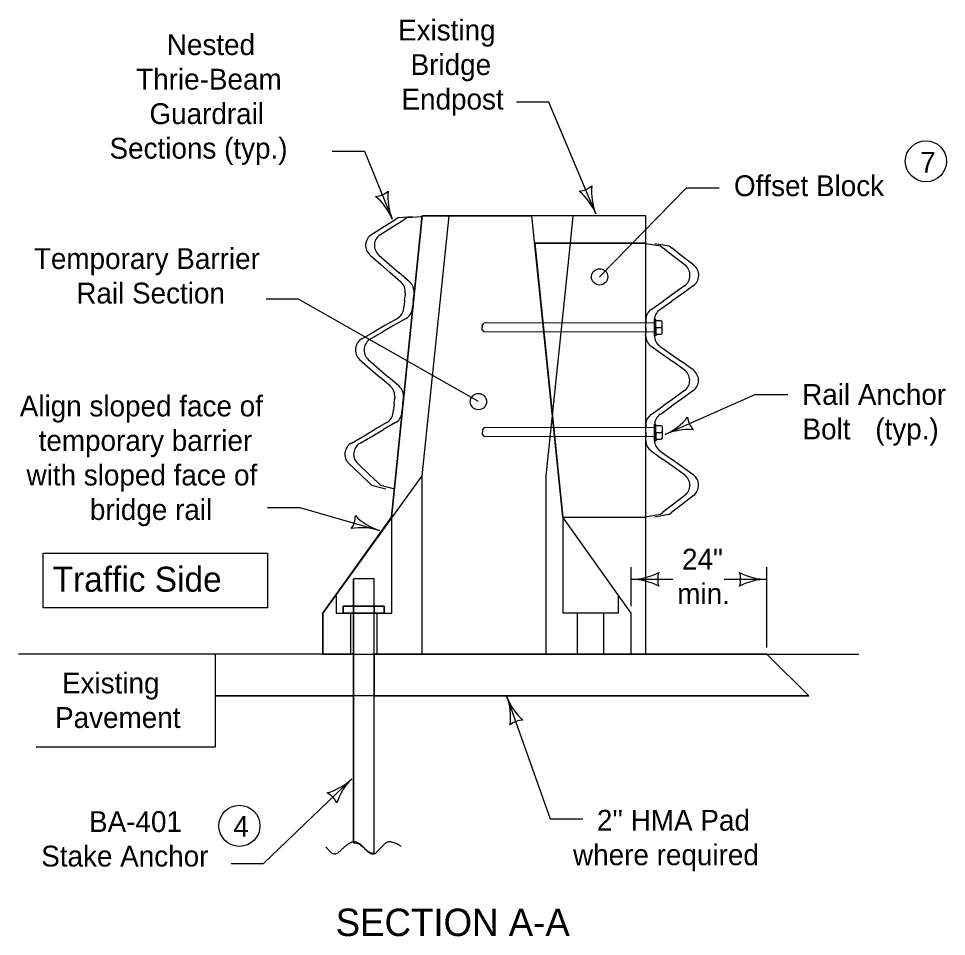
# Model space of a CAD drawing. Extents: x -2137026 to -2131464, y -2138478 to -2136524.
# Drawn here: x -2136990 to -2136313, y -2137286 to -2136616 of the extents above; entities that cross this region are included whole.
import ezdxf

# ---------------------------------------------------------------- set-up
doc = ezdxf.new("R2010")
doc.units = 0
for name, color, linetype in [('conPaving', 7, 'Continuous'), ('Level 2', 7, 'Continuous'), ('Level 3', 7, 'Continuous'), ('Level 41', 7, 'Continuous'), ('Level 9', 7, 'Continuous')]:
    doc.layers.add(name, color=color, linetype=linetype)

msp = doc.modelspace()

# ---------------------------------------------------------------- linework, layer by layer
at = {"layer": 'conPaving'}
for p, q in [((-2136695.79, -2136949.91), (-2136695.79, -2137079.91)), ((-2136605.35, -2136949.91), (-2136605.35, -2137079.91))]:
    msp.add_line(p, q, dxfattribs=at)
at = {"layer": 'Level 2'}
for p, q in [((-2136603.25, -2136676.99), (-2136626.86, -2136676.99)), ((-2136568.93, -2136758.59), (-2136603.25, -2136676.99)), ((-2136761.29, -2136712.88), (-2136737.68, -2136712.88)), ((-2136737.68, -2136712.88), (-2136717.45, -2136762.45)), ((-2136566.1, -2136804.59), (-2136502.64, -2136739.51)), ((-2136502.64, -2136739.51), (-2136479, -2136739.51)), ((-2136718.04, -2136979.91), (-2136695.54, -2136759.91)), ((-2136695.54, -2136759.91), (-2136615.54, -2136759.91)), ((-2136593.04, -2136979.91), (-2136615.54, -2136759.91)), ((-2136723.01, -2136767.65), (-2136715.47, -2136762.89)), ((-2136716.61, -2136767.65), (-2136709.07, -2136762.89)), ((-2136713.24, -2136761.48), (-2136715.47, -2136762.89)), ((-2136702.53, -2136760.66), (-2136713.24, -2136761.48)), ((-2136706.84, -2136761.48), (-2136709.07, -2136762.89)), ((-2136696.13, -2136760.66), (-2136706.84, -2136761.48)), ((-2136732.5, -2136773.64), (-2136723.01, -2136767.65)), ((-2136726.11, -2136773.64), (-2136716.61, -2136767.65)), ((-2136532.36, -2136780.13), (-2136521.78, -2136782.01)), ((-2136525.96, -2136780.13), (-2136515.39, -2136782.01)), ((-2136521.78, -2136782.01), (-2136519.7, -2136783.63)), ((-2136512.67, -2136789.12), (-2136519.7, -2136783.63)), ((-2136515.39, -2136782.01), (-2136513.31, -2136783.63)), ((-2136506.27, -2136789.12), (-2136513.31, -2136783.63)), ((-2136733.67, -2136788.69), (-2136725.87, -2136795.49)), ((-2136727.27, -2136788.69), (-2136719.47, -2136795.49)), ((-2136503.82, -2136796.02), (-2136512.67, -2136789.12)), ((-2136497.42, -2136796.02), (-2136506.27, -2136789.12)), ((-2136725.87, -2136795.49), (-2136719.15, -2136801.35)), ((-2136719.47, -2136795.49), (-2136712.76, -2136801.35)), ((-2136711.14, -2136808.34), (-2136719.15, -2136801.35)), ((-2136704.75, -2136808.34), (-2136712.76, -2136801.35)), ((-2136504.16, -2136811.12), (-2136512.6, -2136817.11)), ((-2136497.77, -2136811.12), (-2136506.2, -2136817.11)), ((-2136785.87, -2136820.95), (-2136809.47, -2136820.95)), ((-2136654.56, -2136895.65), (-2136785.87, -2136820.95)), ((-2136708.5, -2136821.98), (-2136708.13, -2136818.1)), ((-2136707.96, -2136816.35), (-2136708.13, -2136818.1)), ((-2136702.11, -2136821.98), (-2136701.73, -2136818.1)), ((-2136701.56, -2136816.35), (-2136701.73, -2136818.1)), ((-2136512.6, -2136817.11), (-2136519.86, -2136822.27)), ((-2136506.2, -2136817.11), (-2136513.47, -2136822.27)), ((-2136709.05, -2136827.61), (-2136708.85, -2136825.57)), ((-2136708.49, -2136821.84), (-2136708.85, -2136825.57)), ((-2136702.66, -2136827.61), (-2136702.46, -2136825.57)), ((-2136702.09, -2136821.84), (-2136702.46, -2136825.57)), ((-2136528.53, -2136828.43), (-2136519.86, -2136822.27)), ((-2136522.13, -2136828.43), (-2136513.47, -2136822.27)), ((-2136713.73, -2136834.85), (-2136722.92, -2136840.15)), ((-2136707.33, -2136834.85), (-2136716.52, -2136840.15)), ((-2136722.92, -2136840.15), (-2136730.63, -2136844.6)), ((-2136716.52, -2136840.15), (-2136724.24, -2136844.6)), ((-2136532.51, -2136841.59), (-2136532.52, -2136845.35)), ((-2136532.51, -2136841.74), (-2136532.5, -2136837.84)), ((-2136532.5, -2136836.08), (-2136532.5, -2136837.84)), ((-2136526.12, -2136841.59), (-2136526.13, -2136845.35)), ((-2136526.12, -2136841.74), (-2136526.11, -2136837.84)), ((-2136526.1, -2136836.08), (-2136526.11, -2136837.84)), ((-2136739.62, -2136849.78), (-2136730.63, -2136844.6)), ((-2136733.23, -2136849.78), (-2136724.24, -2136844.6)), ((-2136532.53, -2136847.39), (-2136532.52, -2136845.35)), ((-2136526.13, -2136847.39), (-2136526.13, -2136845.35)), ((-2136528.6, -2136855.06), (-2136519.98, -2136861.25)), ((-2136522.2, -2136855.06), (-2136513.59, -2136861.25)), ((-2136519.98, -2136861.25), (-2136512.75, -2136866.45)), ((-2136513.59, -2136861.25), (-2136506.35, -2136866.45)), ((-2136741.36, -2136864.8), (-2136733.29, -2136871.84)), ((-2136734.97, -2136864.8), (-2136726.89, -2136871.84)), ((-2136504.32, -2136872.5), (-2136512.75, -2136866.45)), ((-2136497.92, -2136872.5), (-2136506.35, -2136866.45)), ((-2136733.29, -2136871.84), (-2136726.57, -2136877.7)), ((-2136726.89, -2136871.84), (-2136720.18, -2136877.7)), ((-2136718.84, -2136884.44), (-2136726.57, -2136877.7)), ((-2136712.44, -2136884.44), (-2136720.18, -2136877.7)), ((-2136504.08, -2136887.61), (-2136512.82, -2136893.82)), ((-2136497.68, -2136887.61), (-2136506.42, -2136893.82)), ((-2136716.17, -2136897.77), (-2136715.8, -2136894.03)), ((-2136715.65, -2136892.45), (-2136715.8, -2136894.03)), ((-2136709.77, -2136897.77), (-2136709.41, -2136894.03)), ((-2136709.25, -2136892.45), (-2136709.41, -2136894.03)), ((-2136512.82, -2136893.82), (-2136520.08, -2136898.98)), ((-2136452.33, -2136890.49), (-2136518.23, -2136919.57)), ((-2136506.42, -2136893.82), (-2136513.69, -2136898.98)), ((-2136452.33, -2136890.49), (-2136428.72, -2136890.49)), ((-2136716.75, -2136903.71), (-2136716.53, -2136901.5)), ((-2136716.17, -2136897.77), (-2136716.53, -2136901.5)), ((-2136710.35, -2136903.71), (-2136710.14, -2136901.5)), ((-2136709.77, -2136897.77), (-2136710.14, -2136901.5)), ((-2136528.45, -2136904.92), (-2136520.08, -2136898.98)), ((-2136522.05, -2136904.92), (-2136513.69, -2136898.98)), ((-2136738.04, -2136920.53), (-2136730.32, -2136916.08)), ((-2136731.64, -2136920.53), (-2136723.92, -2136916.08)), ((-2136721.42, -2136910.96), (-2136730.32, -2136916.08)), ((-2136715.03, -2136910.96), (-2136723.92, -2136916.08)), ((-2136532.43, -2136917.91), (-2136532.42, -2136914.16)), ((-2136532.42, -2136912.57), (-2136532.42, -2136914.16)), ((-2136526.04, -2136917.91), (-2136526.03, -2136914.16)), ((-2136526.02, -2136912.57), (-2136526.03, -2136914.16)), ((-2136747.32, -2136925.88), (-2136738.04, -2136920.53)), ((-2136740.92, -2136925.88), (-2136731.64, -2136920.53)), ((-2136532.45, -2136923.89), (-2136532.44, -2136921.66)), ((-2136532.43, -2136917.91), (-2136532.44, -2136921.66)), ((-2136526.04, -2136917.91), (-2136526.05, -2136921.66)), ((-2136526.05, -2136923.89), (-2136526.05, -2136921.66)), ((-2136528.52, -2136931.56), (-2136520.18, -2136937.54)), ((-2136522.12, -2136931.56), (-2136513.78, -2136937.54)), ((-2136749.09, -2136940.88), (-2136740.68, -2136948.82)), ((-2136742.69, -2136940.88), (-2136734.28, -2136948.82)), ((-2136512.94, -2136942.74), (-2136520.18, -2136937.54)), ((-2136506.54, -2136942.74), (-2136513.78, -2136937.54)), ((-2136504.24, -2136948.99), (-2136512.94, -2136942.74)), ((-2136497.84, -2136948.99), (-2136506.54, -2136942.74)), ((-2136740.68, -2136948.82), (-2136734.2, -2136954.95)), ((-2136734.28, -2136948.82), (-2136727.8, -2136954.95)), ((-2136732.53, -2136956.53), (-2136734.2, -2136954.95)), ((-2136732.53, -2136956.53), (-2136722.18, -2136959.4)), ((-2136726.13, -2136956.53), (-2136727.8, -2136954.95)), ((-2136726.13, -2136956.53), (-2136715.78, -2136959.4)), ((-2136503.97, -2136964.09), (-2136513.13, -2136971.15)), ((-2136497.58, -2136964.09), (-2136506.73, -2136971.15)), ((-2136808.55, -2136972.85), (-2136784.95, -2136972.85)), ((-2136784.95, -2136972.85), (-2136726.85, -2136989.7)), ((-2136522.01, -2136978.01), (-2136520.19, -2136976.6)), ((-2136513.13, -2136971.15), (-2136520.19, -2136976.6)), ((-2136515.61, -2136978.01), (-2136513.79, -2136976.6)), ((-2136506.73, -2136971.15), (-2136513.79, -2136976.6)), ((-2136768.04, -2137049.91), (-2136718.04, -2136979.91)), ((-2136543.04, -2137049.91), (-2136593.04, -2136979.91)), ((-2136522.01, -2136978.01), (-2136532.59, -2136979.84)), ((-2136515.61, -2136978.01), (-2136526.2, -2136979.84)), ((-2136543.04, -2137044.92), (-2136543.04, -2137016.56)), ((-2136444, -2137075.15), (-2136444, -2137016.56)), ((-2136543.04, -2137025.32), (-2136512.63, -2137025.32)), ((-2136475.31, -2137025.32), (-2136444, -2137025.32)), ((-2136768.04, -2137079.91), (-2136768.04, -2137049.91)), ((-2136543.04, -2137079.91), (-2136543.04, -2137049.91)), ((-2136768.04, -2137079.91), (-2136543.04, -2137079.91)), ((-2136633.74, -2137111.03), (-2136602.11, -2137200.07)), ((-2136811.38, -2137232.71), (-2136746.96, -2137170.91)), ((-2136602.11, -2137200.07), (-2136578.5, -2137200.07)), ((-2136834.98, -2137232.71), (-2136811.38, -2137232.71))]:
    msp.add_line(p, q, dxfattribs=at)
for centre in [(-2136328.04, -2136720.21), (-2136828.99, -2137205.23)]:
    msp.add_circle(centre, 15, dxfattribs=at)
for centre, radius, start, end in [((-2136582.37, -2136725.59), 16.42, 274.42912, 309.89582), ((-2136529.57, -2136742.56), 42.5, 174.08998, 202.16247), ((-2136730.92, -2136729.46), 16.42, 274.46679, 309.93349), ((-2136756.8, -2136778.51), 42.5, 22.20014, 50.27263), ((-2136678.11, -2136746.4), 42.5, 174.12765, 202.20014), ((-2136608.29, -2136774.63), 42.5, 22.16247, 50.23496), ((-2136535.24, -2136880.63), 42.5, 293.59825, 321.67074), ((-2136485.57, -2136905.31), 16.42, 185.8649, 221.3316), ((-2136501.21, -2136958.52), 42.5, 85.52576, 113.59825), ((-2136760.78, -2136978.8), 16.42, 324.45544, 359.92214), ((-2136713.85, -2136949.23), 42.5, 224.1163, 252.18879), ((-2136739.85, -2137030.16), 42.5, 72.18879, 100.26128), ((-2136543.04, -2136982.82), 42.5, 270, 298.07249), ((-2136507.4, -2137025.32), 16.42, 162.26665, 197.73335), ((-2136479.64, -2137025.32), 16.42, 342.26665, 17.73335), ((-2136444, -2136982.82), 42.5, 241.92751, 270), ((-2136543.04, -2137067.82), 42.5, 61.92751, 90), ((-2136444, -2137067.82), 42.5, 90, 118.07249), ((-2136593.86, -2137096.35), 42.5, 200.20763, 228.28012), ((-2136673.63, -2137125.71), 42.5, 352.13514, 20.20763), ((-2136621.43, -2137144.47), 16.42, 92.47427, 127.94098), ((-2136776.38, -2137140.24), 42.5, 285.73709, 313.80957), ((-2136717.54, -2137201.58), 42.5, 133.80957, 161.88206), ((-2136772.68, -2137195.58), 16.42, 26.07622, 61.54292)]:
    msp.add_arc(centre, radius, start, end, dxfattribs=at)
for centre, major_axis, start_param, end_param in [((-2136727.42, -2136781.6), (9.43, -0.92), 2.229659, 4.096128), ((-2136721.03, -2136781.6), (9.43, -0.92), 2.229659, 4.096128), ((-2136509.67, -2136803.44), (-9.48, 0.02), 2.187057, 4.053527), ((-2136503.27, -2136803.44), (-9.48, 0.02), 2.187057, 4.053527), ((-2136717.39, -2136815.43), (9.43, -0.92), 0, 0.954538), ((-2136710.99, -2136815.43), (9.43, -0.92), 0, 0.954538), ((-2136718.49, -2136826.69), (-9.43, 0.92), 2.187055, 3.141593), ((-2136712.09, -2136826.69), (-9.43, 0.92), 2.187055, 3.141593), ((-2136523.02, -2136836.1), (-9.48, 0.02), 5.328647, 6.283185), ((-2136516.63, -2136836.1), (-9.48, 0.02), 5.328647, 6.283185), ((-2136523.05, -2136847.42), (9.48, -0.02), 3.141593, 4.096131), ((-2136516.65, -2136847.42), (9.48, -0.02), 3.141593, 4.096131), ((-2136734.87, -2136857.94), (-9.43, 0.92), 5.32865, 7.195119), ((-2136728.47, -2136857.94), (-9.43, 0.92), 5.32865, 7.195119), ((-2136509.86, -2136880.14), (9.48, -0.02), 5.371251, 7.237721), ((-2136503.47, -2136880.14), (9.48, -0.02), 5.371251, 7.237721), ((-2136725.08, -2136891.53), (9.43, -0.92), 0, 0.954538), ((-2136718.69, -2136891.53), (9.43, -0.92), 0, 0.954538), ((-2136726.18, -2136902.79), (-9.43, 0.92), 2.187055, 3.141593), ((-2136719.79, -2136902.79), (-9.43, 0.92), 2.187055, 3.141593), ((-2136522.94, -2136912.59), (-9.48, 0.02), 5.328647, 6.283185), ((-2136516.54, -2136912.59), (-9.48, 0.02), 5.328647, 6.283185), ((-2136742.56, -2136934.04), (-9.43, 0.92), 5.32865, 7.195119), ((-2136736.16, -2136934.04), (-9.43, 0.92), 5.32865, 7.195119), ((-2136522.97, -2136923.91), (9.48, -0.02), 3.141593, 4.096131), ((-2136516.57, -2136923.91), (9.48, -0.02), 3.141593, 4.096131), ((-2136509.78, -2136956.63), (9.48, -0.02), 5.371251, 7.237721), ((-2136503.39, -2136956.63), (9.48, -0.02), 5.371251, 7.237721)]:
    msp.add_ellipse(centre, major_axis=major_axis, ratio=0.994906, start_param=start_param, end_param=end_param, dxfattribs=at)
at = {"layer": 'Level 3'}
for p, q in [((-2136676.06, -2136760.02), (-2136695.79, -2136949.91)), ((-2136532.51, -2136760.02), (-2136676.06, -2136760.02)), ((-2136585.63, -2136760.02), (-2136587.7, -2136779.91)), ((-2136532.51, -2137079.8), (-2136532.51, -2136760.02)), ((-2136587.7, -2136779.91), (-2136605.35, -2136949.91)), ((-2136695.79, -2136949.91), (-2136768.04, -2137049.91)), ((-2136768.04, -2137079.91), (-2136768.04, -2137049.91))]:
    msp.add_line(p, q, dxfattribs=at)
at = {"layer": 'Level 41'}
for p, q in [((-2136718.04, -2136979.91), (-2136718.04, -2137049.91)), ((-2136593.04, -2136979.91), (-2136593.04, -2137049.91)), ((-2136758.5, -2137036.56), (-2136758.5, -2137049.91)), ((-2136552.57, -2137036.56), (-2136552.57, -2137049.91)), ((-2136758.5, -2137049.91), (-2136718.04, -2137049.91)), ((-2136747.87, -2137049.91), (-2136747.87, -2137079.91)), ((-2136728.67, -2137049.91), (-2136728.67, -2137079.91)), ((-2136552.57, -2137049.91), (-2136593.04, -2137049.91)), ((-2136582.4, -2137049.91), (-2136582.4, -2137079.91)), ((-2136563.2, -2137049.91), (-2136563.2, -2137079.91))]:
    msp.add_line(p, q, dxfattribs=at)
at = {"layer": 'Level 9'}
for p, q in [((-2136695.54, -2136759.91), (-2136718.04, -2136979.91)), ((-2136615.54, -2136759.91), (-2136695.54, -2136759.91)), ((-2136593.04, -2136979.91), (-2136615.54, -2136759.91)), ((-2136613.49, -2136779.91), (-2136532.51, -2136779.91)), ((-2136532.51, -2136779.91), (-2136613.49, -2136779.91)), ((-2136613.49, -2136779.91), (-2136593.04, -2136979.91)), ((-2136532.51, -2136979.91), (-2136532.51, -2136779.91)), ((-2136651.73, -2136839.95), (-2136650.54, -2136838.33)), ((-2136651.73, -2136839.95), (-2136651.73, -2136841.57)), ((-2136651.73, -2136843.19), (-2136651.73, -2136841.57)), ((-2136526.11, -2136838.35), (-2136650.41, -2136838.15)), ((-2136526.13, -2136847.67), (-2136526.11, -2136835.52)), ((-2136526.12, -2136841.59), (-2136526.11, -2136838.35)), ((-2136526.11, -2136835.52), (-2136525.21, -2136835.52)), ((-2136525.23, -2136846.46), (-2136525.21, -2136836.74)), ((-2136525.22, -2136841.6), (-2136525.23, -2136847.67)), ((-2136525.22, -2136841.6), (-2136525.21, -2136835.52)), ((-2136525.22, -2136841.6), (-2136521.38, -2136841.6)), ((-2136521.37, -2136836.74), (-2136525.21, -2136836.74)), ((-2136520.42, -2136842.47), (-2136520.41, -2136837.61)), ((-2136651.73, -2136843.19), (-2136650.55, -2136844.81)), ((-2136526.12, -2136844.83), (-2136650.69, -2136844.63)), ((-2136525.23, -2136847.67), (-2136526.13, -2136847.67)), ((-2136525.23, -2136846.46), (-2136521.39, -2136846.46)), ((-2136520.42, -2136845.6), (-2136520.42, -2136842.47)), ((-2136651.6, -2136916.41), (-2136650.42, -2136914.79)), ((-2136525.98, -2136914.81), (-2136650.28, -2136914.61)), ((-2136526, -2136924.13), (-2136525.98, -2136911.98)), ((-2136525.99, -2136918.05), (-2136525.98, -2136914.81)), ((-2136525.98, -2136911.98), (-2136525.08, -2136911.98)), ((-2136525.1, -2136922.91), (-2136525.08, -2136913.19)), ((-2136525.09, -2136918.05), (-2136525.08, -2136911.98)), ((-2136521.24, -2136913.2), (-2136525.08, -2136913.19)), ((-2136520.29, -2136918.93), (-2136520.28, -2136914.07)), ((-2136651.6, -2136916.41), (-2136651.6, -2136918.03)), ((-2136651.6, -2136919.65), (-2136651.6, -2136918.03)), ((-2136651.6, -2136919.65), (-2136650.43, -2136921.27)), ((-2136525.99, -2136921.29), (-2136650.56, -2136921.09)), ((-2136525.09, -2136918.05), (-2136525.1, -2136924.13)), ((-2136525.1, -2136922.91), (-2136521.26, -2136922.92)), ((-2136525.09, -2136918.05), (-2136521.25, -2136918.06)), ((-2136520.3, -2136922.06), (-2136520.29, -2136918.93)), ((-2136525.1, -2136924.13), (-2136526, -2136924.13)), ((-2136718.04, -2136979.91), (-2136768.04, -2137049.91)), ((-2136543.04, -2137049.91), (-2136593.04, -2136979.91)), ((-2136593.04, -2136979.91), (-2136532.51, -2136979.91)), ((-2136593.04, -2136979.91), (-2136532.51, -2136979.91)), ((-2136730.77, -2137024.91), (-2136745.77, -2137024.91)), ((-2136745.77, -2137024.91), (-2136745.77, -2137044.91)), ((-2136730.77, -2137024.91), (-2136745.77, -2137024.91)), ((-2136745.77, -2137217.53), (-2136745.77, -2137024.91)), ((-2136730.77, -2137044.91), (-2136730.77, -2137024.91)), ((-2136730.77, -2137225.08), (-2136730.77, -2137024.91)), ((-2136753.27, -2137044.91), (-2136753.27, -2137049.91)), ((-2136745.77, -2137044.91), (-2136753.27, -2137044.91)), ((-2136753.27, -2137049.91), (-2136753.27, -2137044.91)), ((-2136745.77, -2137044.91), (-2136730.77, -2137044.91)), ((-2136730.77, -2137044.91), (-2136745.77, -2137044.91)), ((-2136745.77, -2137044.91), (-2136745.77, -2137049.91)), ((-2136745.77, -2137049.91), (-2136745.77, -2137044.91)), ((-2136730.77, -2137044.91), (-2136730.77, -2137049.91)), ((-2136730.77, -2137049.91), (-2136730.77, -2137044.91)), ((-2136768.04, -2137049.91), (-2136768.04, -2137079.91)), ((-2136753.27, -2137049.91), (-2136745.77, -2137049.91)), ((-2136730.77, -2137049.91), (-2136745.77, -2137049.91)), ((-2136745.77, -2137049.91), (-2136745.77, -2137217.53)), ((-2136745.77, -2137049.91), (-2136730.77, -2137049.91)), ((-2136730.77, -2137225.08), (-2136730.77, -2137049.91)), ((-2136730.77, -2137049.91), (-2136723.27, -2137049.91)), ((-2136543.04, -2137079.91), (-2136543.04, -2137049.91)), ((-2136846.75, -2137079.91), (-2136990.17, -2137079.91)), ((-2136846.75, -2137079.91), (-2136846.75, -2137110.35)), ((-2136768.04, -2137079.91), (-2136846.75, -2137079.91)), ((-2136768.04, -2137079.91), (-2136846.75, -2137079.91)), ((-2136846.75, -2137079.91), (-2136846.75, -2137147.91)), ((-2136747.87, -2137079.91), (-2136768.04, -2137079.91)), ((-2136768.04, -2137079.91), (-2136543.04, -2137079.91)), ((-2136745.77, -2137079.91), (-2136747.87, -2137079.91)), ((-2136745.77, -2137110.35), (-2136745.77, -2137079.91)), ((-2136728.67, -2137079.91), (-2136730.77, -2137079.91)), ((-2136730.77, -2137079.91), (-2136730.77, -2137110.35)), ((-2136582.4, -2137079.91), (-2136728.67, -2137079.91)), ((-2136563.2, -2137079.91), (-2136582.4, -2137079.91)), ((-2136543.04, -2137079.91), (-2136563.2, -2137079.91)), ((-2136444, -2137079.91), (-2136543.04, -2137079.91)), ((-2136543.04, -2137079.91), (-2136376.95, -2137079.91)), ((-2136413.56, -2137110.35), (-2136444, -2137079.91)), ((-2136444, -2137079.91), (-2136413.56, -2137110.35)), ((-2136846.75, -2137110.35), (-2136745.77, -2137110.35)), ((-2136413.56, -2137110.35), (-2136846.75, -2137110.35)), ((-2136730.77, -2137110.35), (-2136413.56, -2137110.35)), ((-2136846.75, -2137147.91), (-2136977.2, -2137147.91))]:
    msp.add_line(p, q, dxfattribs=at)
msp.add_lwpolyline([(-2136972.15, -2137006.21), (-2136808.49, -2137006.21), (-2136808.49, -2137046.21), (-2136972.15, -2137046.21)], close=True, dxfattribs=at)
for points in [[(-2136753.27, -2137044.91), (-2136723.27, -2137044.91), (-2136723.27, -2137049.91), (-2136753.27, -2137049.91)], [(-2136723.27, -2137049.91), (-2136723.27, -2137044.91), (-2136730.77, -2137044.91)]]:
    msp.add_lwpolyline(points, dxfattribs=at)
for centre in [(-2136566.1, -2136804.59), (-2136654.56, -2136895.65)]:
    msp.add_circle(centre, 5.96, dxfattribs=at)
for centre, start_param, end_param in [((-2136521.38, -2136840.74), 1.570796, 3.141593), ((-2136521.38, -2136842.47), 3.141593, 4.712389), ((-2136521.37, -2136837.61), 3.141593, 4.712389), ((-2136521.38, -2136845.6), 1.570796, 3.141593), ((-2136521.24, -2136914.06), 3.141593, 4.712389), ((-2136521.26, -2136922.06), 1.570796, 3.141593), ((-2136521.25, -2136917.2), 1.570796, 3.141593), ((-2136521.25, -2136918.92), 3.141593, 4.712389)]:
    msp.add_ellipse(centre, major_axis=(-0.96, 0.002), ratio=0.899999, start_param=start_param, end_param=end_param, dxfattribs=at)
for points, degree in [([(-2136711.04, -2137220.26), (-2136719.25, -2137214.9), (-2136726.2, -2137221.53), (-2136732.19, -2137228.15), (-2136742.93, -2137215.53), (-2136751.13, -2137219), (-2136759.34, -2137227.84), (-2136765.66, -2137220.9), (-2136765.6, -2137220.92)], 2), ([(-2136745.77, -2137217.53), (-2136744.72, -2137217.46), (-2136740.64, -2137218.22), (-2136734.76, -2137225.14), (-2136731.47, -2137225.25), (-2136730.77, -2137225.08)], 3)]:
    msp.add_open_spline(points, degree=degree, dxfattribs=at)

# ---------------------------------------------------------------- texts
at = {"layer": 'Level 2'}
for s, p in [('7', (-2136332.25, -2136728.57)), ('4', (-2136833.36, -2137213.14))]:
    msp.add_text(s, height=15.2, dxfattribs=at).set_placement(p)
at = {"layer": 'Level 3'}
for s, height, p in [('Existing', 15.2, (-2136713.23, -2136632.06)), ('Nested ', 15.2, (-2136881.98, -2136642.68)), ('Bridge', 15.2, (-2136704.06, -2136657.26)), ('Thrie-Beam', 15.2, (-2136904.33, -2136667.88)), ('Endpost', 15.2, (-2136710.72, -2136682.46)), ('Guardrail ', 15.2, (-2136894.64, -2136693.08)), ('Sections (typ.)', 15.2, (-2136923.79, -2136718.28)), ('Offset Block', 15.2, (-2136468.1, -2136745.67)), ('Temporary Barrier', 15.2, (-2136978.97, -2136798.83)), ('Rail Section', 15.2, (-2136948.03, -2136824.03)), ('Rail Anchor', 15.2, (-2136418.34, -2136897.99)), ('Align sloped face of', 15.2, (-2136989.27, -2136906.41)), ('Bolt ', 15.2, (-2136418.06, -2136923.19)), ('(typ.)', 15.2, (-2136364.96, -2136923.19)), ('temporary barrier', 15.2, (-2136975.52, -2136931.61)), ('with sloped face of ', 15.2, (-2136984.35, -2136956.81)), ('bridge rail', 15.2, (-2136938.1, -2136982.01)), ('24"', 15.2, (-2136505.98, -2137018.22)), ('Traffic Side', 18.24, (-2136965.3, -2137034.36)), ('min.', 15.2, (-2136509.48, -2137043.42)), ('Existing', 15.2, (-2136958.47, -2137108.61)), ('Pavement', 15.2, (-2136963.53, -2137133.81)), ("2'' HMA Pad", 15.2, (-2136568.14, -2137208.77)), ('BA-401', 15.2, (-2136938.73, -2137209.75)), ('Stake Anchor', 15.2, (-2136973.64, -2137234.95)), ('where required', 15.2, (-2136585.52, -2137233.97)), ('SECTION A-A', 20, (-2136758.78, -2137285.68))]:
    msp.add_text(s, height=height, dxfattribs=at).set_placement(p)

doc.saveas('drawing.dxf')
